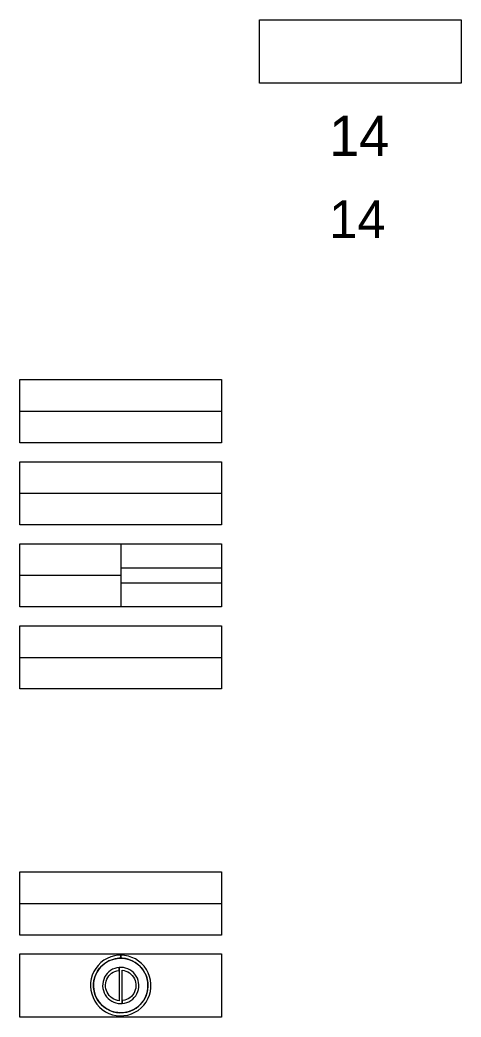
# Model space of a CAD drawing. Extents: x -477745 to -465038, y -1159336 to -1148316.
# Drawn here: x -467865 to -467603, y -1158629 to -1158036 of the extents above; entities that cross this region are included whole.
import ezdxf

# ---------------------------------------------------------------- set-up
doc = ezdxf.new("R2010")
doc.units = 0
for name, color, linetype in [('kraj_prvek stab', 7, 'Continuous'), ('popis_plochy', 7, 'Continuous'), ('Vrstva 4', 7, 'Continuous'), ('Vrstva 5', 7, 'Continuous'), ('Vrstva 53', 7, 'Continuous'), ('Vrstva 60', 7, 'Continuous'), ('ZASTAVENE', 7, 'Continuous')]:
    doc.layers.add(name, color=color, linetype=linetype)

msp = doc.modelspace()

# ---------------------------------------------------------------- linework, layer by layer
at = {"layer": 'kraj_prvek stab'}
msp.add_line((-467804.27, -1158620.89), (-467804.27, -1158620.89), dxfattribs=at)
for points in [[(-467805.21, -1158592.14), (-467806.71, -1158592.2), (-467808.96, -1158592.54), (-467811.15, -1158593.15), (-467813.25, -1158594.04), (-467815.22, -1158595.18), (-467817.03, -1158596.57), (-467818.65, -1158598.17), (-467820.05, -1158599.96), (-467821.22, -1158601.91), (-467822.13, -1158604), (-467822.77, -1158606.19), (-467823.13, -1158608.43), (-467823.2, -1158610.71), (-467822.99, -1158612.98), (-467822.49, -1158615.2), (-467821.71, -1158617.34), (-467820.68, -1158619.37), (-467819.39, -1158621.25), (-467817.88, -1158622.95), (-467816.16, -1158624.44), (-467814.27, -1158625.71), (-467812.23, -1158626.73), (-467810.09, -1158627.49), (-467807.86, -1158627.97), (-467805.59, -1158628.16), (-467803.31, -1158628.06), (-467801.07, -1158627.68), (-467798.89, -1158627.02), (-467796.81, -1158626.09), (-467794.87, -1158624.91), (-467793.09, -1158623.48), (-467791.5, -1158621.85), (-467790.14, -1158620.03), (-467789.01, -1158618.05), (-467788.14, -1158615.94), (-467787.55, -1158613.74), (-467787.24, -1158611.49), (-467787.21, -1158609.21), (-467787.47, -1158606.95), (-467788.02, -1158604.74), (-467788.84, -1158602.61), (-467789.92, -1158600.61), (-467791.25, -1158598.76), (-467792.8, -1158597.09), (-467794.55, -1158595.63), (-467796.46, -1158594.4), (-467798.52, -1158593.42), (-467800.68, -1158592.72), (-467802.92, -1158592.28), (-467805.19, -1158592.14)], [(-467805.21, -1158593.94), (-467805.21, -1158592.14)], [(-467805.19, -1158592.14), (-467805.19, -1158593.94)], [(-467788.99, -1158610.15), (-467789.12, -1158608.11), (-467789.5, -1158606.09), (-467790.14, -1158604.15), (-467791.02, -1158602.29), (-467792.12, -1158600.57), (-467793.44, -1158598.99), (-467794.94, -1158597.6), (-467796.61, -1158596.4), (-467798.41, -1158595.43), (-467800.32, -1158594.69), (-467802.31, -1158594.2), (-467804.35, -1158593.96), (-467806.4, -1158593.98), (-467808.43, -1158594.26), (-467810.4, -1158594.8), (-467812.3, -1158595.58), (-467814.08, -1158596.59), (-467815.72, -1158597.82), (-467817.2, -1158599.24), (-467818.47, -1158600.85), (-467819.54, -1158602.6), (-467820.38, -1158604.47), (-467820.98, -1158606.43), (-467821.32, -1158608.45), (-467821.41, -1158610.49), (-467821.23, -1158612.54), (-467820.81, -1158614.54), (-467820.13, -1158616.48), (-467819.21, -1158618.31), (-467818.07, -1158620.01), (-467816.72, -1158621.56), (-467815.19, -1158622.92), (-467813.5, -1158624.08), (-467811.68, -1158625.01), (-467809.75, -1158625.71), (-467807.75, -1158626.16), (-467805.71, -1158626.36), (-467803.66, -1158626.29), (-467801.64, -1158625.97), (-467799.67, -1158625.39), (-467797.79, -1158624.57), (-467796.03, -1158623.52), (-467794.42, -1158622.26), (-467792.98, -1158620.8), (-467791.73, -1158619.17), (-467790.7, -1158617.4), (-467789.9, -1158615.51), (-467789.35, -1158613.54), (-467789.04, -1158611.51), (-467788.99, -1158610.15)], [(-467805.19, -1158593.94), (-467803.85, -1158594), (-467801.82, -1158594.3), (-467799.84, -1158594.85), (-467797.96, -1158595.65), (-467796.18, -1158596.68), (-467794.56, -1158597.92), (-467793.1, -1158599.36), (-467791.83, -1158600.98), (-467790.78, -1158602.74), (-467789.96, -1158604.61), (-467789.39, -1158606.58), (-467789.06, -1158608.6), (-467789, -1158610.65), (-467789.19, -1158612.69), (-467789.64, -1158614.69), (-467790.33, -1158616.62), (-467791.27, -1158618.44), (-467792.43, -1158620.14), (-467793.79, -1158621.67), (-467795.33, -1158623.02), (-467797.04, -1158624.16), (-467798.87, -1158625.08), (-467800.8, -1158625.76), (-467802.81, -1158626.18), (-467804.85, -1158626.36), (-467806.9, -1158626.27), (-467808.92, -1158625.93), (-467810.88, -1158625.34), (-467812.75, -1158624.5), (-467814.5, -1158623.43), (-467816.1, -1158622.15), (-467817.53, -1158620.68), (-467818.76, -1158619.04), (-467819.77, -1158617.26), (-467820.55, -1158615.36), (-467821.09, -1158613.39), (-467821.37, -1158611.36), (-467821.39, -1158609.31), (-467821.15, -1158607.27), (-467820.66, -1158605.28), (-467819.92, -1158603.37), (-467818.95, -1158601.56), (-467817.76, -1158599.9), (-467816.36, -1158598.4), (-467814.79, -1158597.08), (-467813.06, -1158595.97), (-467811.21, -1158595.1), (-467809.26, -1158594.46), (-467807.25, -1158594.07), (-467805.21, -1158593.94)], [(-467806.13, -1158599.41), (-467807.48, -1158599.61), (-467808.79, -1158599.99), (-467810.05, -1158600.52), (-467811.22, -1158601.21), (-467812.3, -1158602.04), (-467813.27, -1158603), (-467814.11, -1158604.08), (-467814.8, -1158605.25), (-467815.34, -1158606.5), (-467815.72, -1158607.81), (-467815.93, -1158609.16), (-467815.97, -1158610.52), (-467815.84, -1158611.88), (-467815.54, -1158613.2), (-467815.07, -1158614.48), (-467814.45, -1158615.7), (-467813.67, -1158616.82), (-467812.76, -1158617.84), (-467811.73, -1158618.73), (-467810.6, -1158619.48), (-467809.38, -1158620.09), (-467808.09, -1158620.54), (-467806.76, -1158620.82), (-467805.4, -1158620.93), (-467804.34, -1158620.9)], [(-467806.06, -1158619.17), (-467807.19, -1158618.98), (-467808.29, -1158618.66), (-467809.34, -1158618.2), (-467810.32, -1158617.62), (-467811.22, -1158616.91), (-467812.03, -1158616.1), (-467812.73, -1158615.19), (-467813.3, -1158614.2), (-467813.75, -1158613.14), (-467814.06, -1158612.04), (-467814.22, -1158610.91), (-467814.25, -1158609.76), (-467814.12, -1158608.63), (-467813.86, -1158607.51), (-467813.46, -1158606.44), (-467812.93, -1158605.43), (-467812.27, -1158604.49), (-467811.5, -1158603.64), (-467810.63, -1158602.9), (-467809.67, -1158602.27), (-467808.64, -1158601.77), (-467807.55, -1158601.4), (-467806.43, -1158601.18), (-467806.13, -1158601.14)], [(-467806.13, -1158601.14), (-467806.13, -1158599.41)], [(-467804.27, -1158620.89), (-467802.92, -1158620.69), (-467801.61, -1158620.32), (-467800.35, -1158619.78), (-467799.18, -1158619.09), (-467798.1, -1158618.26), (-467797.13, -1158617.3), (-467796.29, -1158616.22), (-467795.6, -1158615.05), (-467795.05, -1158613.8), (-467794.68, -1158612.49), (-467794.47, -1158611.15), (-467794.42, -1158609.78), (-467794.56, -1158608.43), (-467794.86, -1158607.1), (-467795.33, -1158605.82), (-467795.95, -1158604.61), (-467796.73, -1158603.48), (-467797.64, -1158602.47), (-467798.66, -1158601.58), (-467799.8, -1158600.82), (-467801.02, -1158600.21), (-467802.31, -1158599.77), (-467803.64, -1158599.48), (-467805, -1158599.37), (-467806.06, -1158599.4)], [(-467806.06, -1158599.4), (-467806.06, -1158619.17)], [(-467804.34, -1158620.9), (-467804.34, -1158601.13)], [(-467804.34, -1158601.13), (-467803.21, -1158601.32), (-467802.11, -1158601.64), (-467801.06, -1158602.1), (-467800.07, -1158602.68), (-467799.18, -1158603.39), (-467798.37, -1158604.2), (-467797.67, -1158605.12), (-467797.1, -1158606.1), (-467796.65, -1158607.16), (-467796.34, -1158608.26), (-467796.18, -1158609.39), (-467796.15, -1158610.54), (-467796.27, -1158611.68), (-467796.54, -1158612.79), (-467796.94, -1158613.86), (-467797.47, -1158614.87), (-467798.13, -1158615.81), (-467798.9, -1158616.66), (-467799.77, -1158617.4), (-467800.73, -1158618.03), (-467801.76, -1158618.53), (-467802.85, -1158618.9), (-467803.97, -1158619.12), (-467804.27, -1158619.16)], [(-467804.27, -1158619.16), (-467804.27, -1158620.89)]]:
    msp.add_lwpolyline(points, dxfattribs=at)
at = {"layer": 'Vrstva 4'}
msp.add_line((-467865.2, -1158268.9), (-467745.2, -1158268.9), dxfattribs=at)
at = {"layer": 'Vrstva 5'}
for p, q in [((-467865.2, -1158317.65), (-467745.2, -1158317.65)), ((-467865.2, -1158366.4), (-467805.2, -1158366.4)), ((-467865.2, -1158415.15), (-467745.2, -1158415.15))]:
    msp.add_line(p, q, dxfattribs=at)
at = {"layer": 'Vrstva 53'}
msp.add_line((-467865.2, -1158561.4), (-467745.2, -1158561.4), dxfattribs=at)
at = {"layer": 'Vrstva 60'}
for p, q in [((-467805.2, -1158347.65), (-467805.2, -1158385.15)), ((-467805.2, -1158361.9), (-467745.2, -1158361.9)), ((-467805.2, -1158370.9), (-467745.2, -1158370.9))]:
    msp.add_line(p, q, dxfattribs=at)
for points in [[(-467865.2, -1158250.15), (-467745.2, -1158250.15), (-467745.2, -1158287.65), (-467865.2, -1158287.65)], [(-467865.2, -1158298.9), (-467745.2, -1158298.9), (-467745.2, -1158336.4), (-467865.2, -1158336.4)], [(-467865.2, -1158347.65), (-467745.2, -1158347.65), (-467745.2, -1158385.15), (-467865.2, -1158385.15)], [(-467865.2, -1158396.4), (-467745.2, -1158396.4), (-467745.2, -1158433.9), (-467865.2, -1158433.9)], [(-467865.2, -1158542.65), (-467745.2, -1158542.65), (-467745.2, -1158580.15), (-467865.2, -1158580.15)], [(-467865.2, -1158591.4), (-467745.2, -1158591.4), (-467745.2, -1158628.9), (-467865.2, -1158628.9)]]:
    msp.add_lwpolyline(points, close=True, dxfattribs=at)
at = {"layer": 'ZASTAVENE'}
msp.add_lwpolyline([(-467722.7, -1158036.4), (-467602.7, -1158036.4), (-467602.7, -1158073.9), (-467722.7, -1158073.9)], close=True, dxfattribs=at)

# ---------------------------------------------------------------- texts
at = {"layer": 'popis_plochy'}
for height, p in [(24, (-467681.15, -1158117.32)), (22.5, (-467681.15, -1158166.07))]:
    msp.add_text('14', height=height, dxfattribs=at).set_placement(p)

doc.saveas('drawing.dxf')
